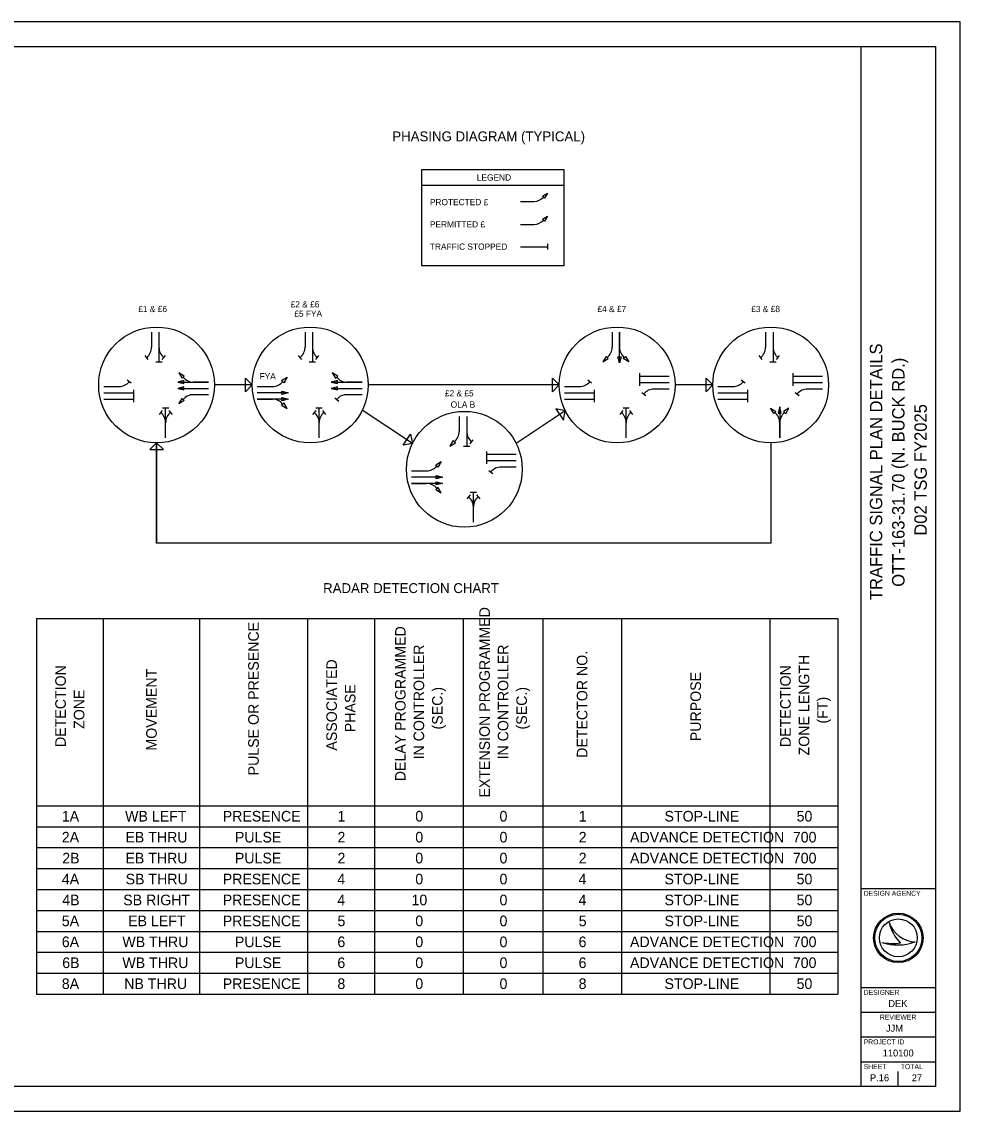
# Model space of a CAD drawing. Extents: x 0 to 680, y 0 to 440.
# Drawn here: x 300.9 to 680, y 0 to 440 of the extents above; entities that cross this region are included whole.
import ezdxf

# ---------------------------------------------------------------- set-up
doc = ezdxf.new("R2010")
doc.units = 0
for name, color, linetype in [('SH_Border', 7, 'Continuous'), ('SH_Cut_Line', 7, 'Continuous'), ('SH_Data', 7, 'Continuous'), ('SH_Text', 7, 'Continuous')]:
    doc.layers.add(name, color=color, linetype=linetype)

msp = doc.modelspace()

# ---------------------------------------------------------------- linework, layer by layer
at = {"layer": 'SH_Border'}
for p, q in [((640, 10), (640, 430)), ((640, 90), (670, 90)), ((640, 50), (670, 50)), ((640, 40), (670, 40)), ((640, 30), (670, 30)), ((640, 20), (670, 20))]:
    msp.add_line(p, q, dxfattribs=at)
msp.add_lwpolyline([(30, 430), (670, 430), (670, 10), (30, 10)], close=True, dxfattribs=at)
at = {"layer": 'SH_Cut_Line'}
msp.add_lwpolyline([(0, 0), (680, 0), (680, 440), (0, 440)], close=True, dxfattribs=at)
at = {"layer": 'SH_Data'}
for p, q in [((462.45, 373.97), (520.09, 373.97)), ((502.43, 367.44), (507.93, 367.44)), ((502.43, 358.14), (507.93, 358.14)), ((502.43, 349.14), (513.24, 349.14)), ((513.24, 350.28), (513.24, 348)), ((353.35, 314.68), (353.35, 308.57)), ((356.34, 314.68), (356.34, 308.57)), ((356.34, 314.68), (356.34, 302.67)), ((415.36, 314.68), (415.36, 308.57)), ((418.35, 314.68), (418.35, 308.57)), ((418.35, 314.68), (418.35, 302.67)), ((539.39, 314.68), (539.39, 308.57)), ((542.38, 314.68), (542.38, 308.57)), ((542.38, 302.22), (542.38, 314.68)), ((601.4, 314.68), (601.4, 308.57)), ((604.39, 314.68), (604.39, 308.57)), ((604.39, 314.68), (604.39, 302.67)), ((352.01, 303.64), (350.73, 305.24)), ((357.68, 303.64), (358.96, 305.24)), ((414.02, 303.64), (412.74, 305.24)), ((419.69, 303.64), (420.97, 305.24)), ((600.06, 303.64), (598.78, 305.24)), ((605.73, 303.64), (607.01, 305.24)), ((355.07, 302.67), (357.61, 302.67)), ((417.08, 302.67), (419.62, 302.67)), ((603.12, 302.67), (605.66, 302.67)), ((345.09, 294.01), (343.5, 295.29)), ((531.13, 294.01), (529.54, 295.29)), ((550.41, 298.02), (550.41, 295.49)), ((562.42, 296.76), (550.41, 296.76)), ((550.41, 295.49), (550.41, 292.95)), ((593.15, 294.01), (591.55, 295.29)), ((612.42, 298.02), (612.42, 295.49)), ((624.43, 296.76), (612.42, 296.76)), ((612.42, 295.49), (612.42, 292.95)), ((334.06, 292.66), (340.17, 292.67)), ((346.07, 291.4), (346.07, 288.86)), ((363.92, 294.47), (376.38, 294.47)), ((363.92, 291.94), (376.38, 291.94)), ((376.38, 294.47), (370.27, 294.47)), ((394.01, 293.32), (378.79, 293.32)), ((396.07, 292.66), (402.18, 292.66)), ((425.93, 294.47), (438.39, 294.47)), ((425.93, 291.94), (438.39, 291.94)), ((438.39, 294.47), (432.28, 294.47)), ((518.04, 293.32), (440.8, 293.32)), ((520.1, 292.66), (526.21, 292.67)), ((532.11, 291.4), (532.11, 288.86)), ((562.42, 294.22), (550.41, 294.22)), ((562.42, 291.68), (556.31, 291.68)), ((580.05, 293.32), (564.83, 293.32)), ((582.11, 292.66), (588.22, 292.67)), ((594.12, 291.4), (594.12, 288.86)), ((624.43, 294.22), (612.42, 294.22)), ((624.43, 291.68), (618.32, 291.68)), ((334.06, 290.13), (346.07, 290.13)), ((334.06, 287.59), (346.07, 287.59)), ((346.07, 288.86), (346.07, 286.32)), ((376.38, 289.4), (370.27, 289.4)), ((408.53, 290.13), (396.07, 290.13)), ((408.53, 287.59), (396.07, 287.59)), ((396.07, 287.59), (402.18, 287.59)), ((427.35, 288.06), (428.95, 286.78)), ((438.39, 289.4), (432.28, 289.4)), ((520.1, 290.13), (532.11, 290.13)), ((520.1, 287.59), (532.11, 287.59)), ((532.11, 288.86), (532.11, 286.32)), ((551.38, 290.34), (552.97, 289.06)), ((582.11, 290.13), (594.12, 290.13)), ((582.11, 287.59), (594.12, 287.59)), ((594.12, 288.86), (594.12, 286.32)), ((613.39, 290.34), (614.99, 289.06)), ((357.69, 283.02), (356.41, 281.42)), ((360.3, 283.99), (357.76, 283.99)), ((359.03, 271.98), (359.03, 283.99)), ((360.37, 283.02), (361.65, 281.42)), ((419.7, 283.02), (418.42, 281.42)), ((422.31, 283.99), (419.77, 283.99)), ((421.04, 271.98), (421.04, 283.99)), ((422.38, 283.02), (423.66, 281.42)), ((458.78, 269.73), (438.49, 283.18)), ((520.49, 282.9), (500.63, 269.73)), ((543.73, 283.02), (542.45, 281.42)), ((546.34, 283.99), (543.8, 283.99)), ((545.07, 271.98), (545.07, 283.99)), ((546.41, 283.02), (547.69, 281.42)), ((607.08, 284.44), (607.08, 271.98)), ((359.03, 271.98), (359.03, 278.09)), ((359.03, 271.98), (359.03, 278.09)), ((421.04, 271.98), (421.04, 278.09)), ((421.04, 271.98), (421.04, 278.09)), ((477.66, 280.63), (477.66, 274.52)), ((480.65, 280.63), (480.65, 268.62)), ((480.65, 280.63), (480.65, 274.52)), ((545.07, 271.98), (545.07, 278.09)), ((545.07, 271.98), (545.07, 278.09)), ((607.08, 271.98), (607.08, 278.09)), ((607.08, 271.98), (607.08, 278.09)), ((355.39, 269.92), (355.39, 229.36)), ((479.38, 268.62), (481.92, 268.62)), ((481.99, 269.59), (483.27, 271.19)), ((603.45, 269.92), (603.45, 229.36)), ((488.67, 266.51), (488.67, 263.97)), ((500.69, 265.24), (488.67, 265.24)), ((488.67, 263.97), (488.67, 261.44)), ((500.69, 262.71), (488.67, 262.71)), ((500.69, 260.17), (494.58, 260.17)), ((458.36, 258.62), (464.48, 258.62)), ((470.82, 256.08), (458.36, 256.08)), ((489.65, 258.83), (491.24, 257.55)), ((470.82, 253.54), (458.36, 253.54)), ((458.36, 253.54), (464.48, 253.54)), ((482, 248.97), (480.72, 247.38)), ((484.6, 249.94), (482.07, 249.94)), ((483.34, 237.93), (483.34, 249.94)), ((484.67, 248.97), (485.96, 247.38)), ((483.34, 237.93), (483.34, 244.04)), ((483.34, 237.93), (483.34, 244.04)), ((306.82, 199.03), (630.63, 199.03)), ((306.82, 199.03), (306.82, 47.27)), ((333.87, 199.03), (333.87, 47.27)), ((372.76, 199.03), (372.76, 47.27)), ((416.31, 199.03), (416.31, 47.27)), ((443.36, 199.03), (443.36, 47.27)), ((479.29, 199.03), (479.29, 47.27)), ((511.42, 199.03), (511.42, 47.27)), ((543.12, 199.03), (543.12, 47.27)), ((603.15, 199.03), (603.15, 47.27)), ((630.63, 199.03), (630.63, 47.27)), ((306.82, 123.36), (630.63, 123.36)), ((306.82, 114.91), (630.63, 114.91)), ((306.82, 106.45), (630.63, 106.45)), ((306.82, 98), (630.63, 98)), ((306.82, 89.55), (630.63, 89.55)), ((306.82, 81.09), (630.63, 81.09)), ((651.35, 76.19), (651.35, 76.19)), ((306.82, 72.64), (630.63, 72.64)), ((648.34, 68.19), (648.34, 68.19)), ((655, 70), (655, 70)), ((661.75, 68.37), (661.75, 68.37)), ((306.82, 64.18), (630.63, 64.18)), ((306.82, 55.73), (630.63, 55.73)), ((306.82, 47.27), (630.63, 47.27)), ((647.5, 13.5), (647.5, 13.5)), ((655, 10), (655, 16))]:
    msp.add_line(p, q, dxfattribs=at)
for points in [[(520.09, 380.27), (462.45, 380.27), (462.45, 341.58), (520.09, 341.58)], [(511.25, 369.62), (513.24, 370.82), (512.04, 368.83)], [(511.25, 360.32), (513.24, 361.51), (512.04, 359.52)], [(536.97, 304.88), (535.64, 302.67), (537.85, 304)], [(543, 304.72), (542.38, 302.22), (541.75, 304.72)], [(544.8, 304.88), (546.12, 302.67), (543.92, 304)], [(366.42, 295.1), (363.92, 294.47), (366.42, 293.85)], [(366.58, 296.9), (364.37, 298.22), (365.7, 296.01)], [(394.01, 293.32), (391.29, 290.59), (391.29, 296.04)], [(405.87, 295.09), (408.08, 296.41), (406.75, 294.2)], [(428.43, 295.1), (425.93, 294.47), (428.43, 293.85)], [(428.59, 296.9), (426.38, 298.22), (427.71, 296.01)], [(518.04, 293.32), (515.31, 290.59), (515.31, 296.04)], [(580.05, 293.32), (577.33, 290.59), (577.32, 296.04)], [(366.42, 292.56), (363.92, 291.94), (366.42, 291.31)], [(406.03, 290.75), (408.53, 290.13), (406.03, 289.5)], [(428.43, 292.56), (425.93, 291.94), (428.43, 291.31)], [(366.58, 286.98), (364.37, 285.65), (365.7, 287.86)], [(405.87, 285.17), (408.08, 283.84), (406.75, 286.05)], [(406.03, 288.22), (408.53, 287.59), (406.03, 286.97)], [(520.49, 282.9), (516.71, 283.66), (519.72, 279.12)], [(604.66, 281.78), (603.34, 283.99), (605.54, 282.66)], [(607.71, 281.94), (607.08, 284.44), (606.46, 281.94)], [(609.5, 281.78), (610.83, 283.99), (608.62, 282.66)], [(458.78, 269.73), (455, 268.96), (458.01, 273.51)], [(355.39, 269.92), (352.67, 267.2), (358.12, 267.19)], [(475.24, 270.83), (473.91, 268.62), (476.12, 269.95)], [(468.16, 261.04), (470.38, 262.36), (469.05, 260.16)], [(468.32, 256.71), (470.82, 256.08), (468.32, 255.45)], [(468.16, 251.12), (470.38, 249.8), (469.05, 252)], [(468.32, 254.17), (470.82, 253.54), (468.32, 252.92)]]:
    msp.add_lwpolyline(points, close=True, dxfattribs=at)
msp.add_lwpolyline([(603.45, 269.92), (603.45, 269.92), (603.45, 229.36), (355.39, 229.36), (355.39, 229.36), (355.39, 269.92), (355.39, 269.92)], dxfattribs=at)
for centre, radius in [((355.39, 293.32), 23.39), ((417.41, 293.32), 23.39), ((541.43, 293.32), 23.39), ((603.45, 293.32), 23.39), ((479.7, 259.27), 23.39), ((655, 70), 10), ((655, 70), 9.54), ((655, 70), 9.54), ((655, 70), 7.64)]:
    msp.add_circle(centre, radius, dxfattribs=at)
for centre, radius, start, end in [((507.93, 372.21), 4.77, 270.0129, 321.2136), ((507.93, 362.91), 4.77, 270, 321.2007), ((348.05, 308.57), 5.3, 308.7993, 0), ((361.64, 308.57), 5.3, 180, 231.2007), ((410.06, 308.57), 5.3, 308.7993, 0), ((423.65, 308.57), 5.3, 180, 231.2007), ((534.09, 308.57), 5.3, 308.7993, 0), ((547.68, 308.57), 5.3, 180, 231.2007), ((596.1, 308.57), 5.3, 308.7993, 0), ((609.69, 308.57), 5.3, 180, 231.2007), ((370.27, 299.77), 5.3, 218.7864, 269.9871), ((432.28, 299.77), 5.3, 218.7864, 269.9871), ((340.17, 297.97), 5.3, 270.0129, 321.2136), ((402.18, 297.96), 5.3, 270, 321.2007), ((526.21, 297.97), 5.3, 270.0129, 321.2136), ((556.31, 286.38), 5.3, 90.0129, 141.2136), ((588.22, 297.97), 5.3, 270.0129, 321.2136), ((618.32, 286.38), 5.3, 90.0129, 141.2136), ((370.27, 284.1), 5.3, 90.0129, 141.2136), ((402.18, 282.29), 5.3, 38.7864, 89.9871), ((432.28, 284.1), 5.3, 90.0129, 141.2136), ((353.73, 278.09), 5.3, 360, 51.2007), ((364.33, 278.09), 5.3, 128.7993, 180), ((415.74, 278.09), 5.3, 360, 51.2007), ((426.34, 278.09), 5.3, 128.7993, 180), ((539.77, 278.09), 5.3, 360, 51.2007), ((550.37, 278.09), 5.3, 128.7993, 180), ((601.78, 278.09), 5.3, 360, 51.2007), ((612.38, 278.09), 5.3, 128.7993, 180), ((472.36, 274.52), 5.3, 308.7993, 0), ((485.95, 274.52), 5.3, 180, 231.2007), ((464.47, 263.92), 5.3, 270.0129, 321.2136), ((494.58, 254.87), 5.3, 90.0129, 141.2136), ((464.47, 248.24), 5.3, 38.7864, 89.9871), ((478.04, 244.04), 5.3, 360, 51.2007), ((488.64, 244.04), 5.3, 128.7993, 180), ((662.32, 79.95), 11.6, 198.9257, 198.9319), ((666.93, 79.4), 15.91, 191.6379, 191.6421), ((662.32, 79.95), 11.6, 198.9319, 267.1657), ((666.93, 79.4), 15.91, 191.6421, 226.0947), ((654.79, 87.4), 20.26, 251.4576, 290.0832), ((652.96, 93.09), 25.32, 259.4964, 259.4995), ((654.79, 87.4), 20.26, 251.4527, 251.4576), ((652.96, 93.09), 25.32, 259.4995, 276.6672)]:
    msp.add_arc(centre, radius, start, end, dxfattribs=at)

# ---------------------------------------------------------------- texts
for s, height, p in [('TRAFFIC SIGNAL PLAN DETAILS', 5, (648.5, 206.42)), ('OTT-163-31.70 (N. BUCK RD.)', 5, (657.5, 211.8)), ('D02 TSG FY2025', 5, (666.5, 232.44)), ('EXTENSION PROGRAMMED', 4.278, (490.01, 126.68)), ('PULSE OR PRESENCE', 4.278, (396.67, 135.64)), ('DELAY PROGRAMMED', 4.278, (455.98, 133.26)), (' IN CONTROLLER', 4.278, (463.47, 140.48)), (' IN CONTROLLER', 4.278, (497.49, 140.48)), ('DETECTOR NO.', 4.278, (529.41, 142.71)), ('ASSOCIATED', 4.278, (428.23, 145.64)), ('ZONE LENGTH', 4.278, (619.03, 143.69)), ('DETECTION', 4.278, (318.74, 147.1)), ('MOVEMENT', 4.278, (355.46, 145.66)), ('PURPOSE', 4.278, (575.28, 149.45)), ('DETECTION', 4.278, (611.54, 147.1)), ('PHASE', 4.278, (435.71, 153.05)), ('ZONE', 4.278, (326.23, 154.4)), ('(SEC.)', 4.278, (470.95, 154.18)), ('(SEC.)', 4.278, (504.98, 154.18)), ('(FT)', 4.278, (626.52, 156.57))]:
    msp.add_text(s, height=height, rotation=90, dxfattribs=at).set_placement(p)
for s, height, p in [('1A', 4.278, (317.11, 117)), ('WB LEFT', 4.278, (342.68, 117)), ('PRESENCE', 4.278, (382.1, 117)), ('1', 4.28, (428.46, 117)), ('0', 4.28, (459.89, 117)), ('0', 4.28, (493.92, 117)), ('1', 4.28, (525.9, 117)), ('STOP-LINE', 4.278, (560.55, 117)), ('50', 4.278, (613.92, 117)), ('2A', 4.278, (317.11, 108.54)), ('EB THRU', 4.278, (342.79, 108.54)), ('PULSE', 4.278, (387.03, 108.54)), ('2', 4.28, (428.46, 108.54)), ('0', 4.28, (459.89, 108.54)), ('0', 4.28, (493.92, 108.54)), ('2', 4.28, (525.9, 108.54)), ('ADVANCE DETECTION', 4.278, (546.62, 108.54)), ('700', 4.278, (612.39, 108.54)), ('2B', 4.278, (317.29, 100.09)), ('EB THRU', 4.278, (342.79, 100.09)), ('PULSE', 4.278, (387.03, 100.09)), ('2', 4.28, (428.46, 100.09)), ('0', 4.28, (459.89, 100.09)), ('0', 4.28, (493.92, 100.09)), ('2', 4.28, (525.9, 100.09)), ('ADVANCE DETECTION', 4.278, (546.62, 100.09)), ('700', 4.278, (612.39, 100.09)), ('4A', 4.278, (317.11, 91.63)), ('SB THRU', 4.278, (342.88, 91.63)), ('PRESENCE', 4.278, (382.1, 91.63)), ('4', 4.28, (428.38, 91.63)), ('0', 4.28, (459.89, 91.63)), ('0', 4.28, (493.92, 91.63)), ('4', 4.28, (525.82, 91.63)), ('STOP-LINE', 4.278, (560.55, 91.63)), ('50', 4.278, (613.92, 91.63)), ('DESIGN AGENCY', 2, (641, 87)), ('4B', 4.278, (317.29, 83.18)), ('SB RIGHT', 4.278, (341.92, 83.18)), ('PRESENCE', 4.278, (382.1, 83.18)), ('4', 4.28, (428.38, 83.18)), ('10', 4.278, (458.36, 83.18)), ('0', 4.28, (493.92, 83.18)), ('4', 4.28, (525.82, 83.18)), ('STOP-LINE', 4.278, (560.55, 83.18)), ('50', 4.278, (613.92, 83.18)), ('5A', 4.278, (317.11, 74.72)), ('EB LEFT', 4.278, (343.9, 74.72)), ('PRESENCE', 4.278, (382.1, 74.72)), ('5', 4.28, (428.47, 74.72)), ('0', 4.28, (459.89, 74.72)), ('0', 4.28, (493.92, 74.72)), ('5', 4.28, (525.91, 74.72)), ('STOP-LINE', 4.278, (560.55, 74.72)), ('50', 4.278, (613.92, 74.72)), ('6A', 4.278, (317.11, 66.27)), ('WB THRU', 4.278, (341.57, 66.27)), ('PULSE', 4.278, (387.03, 66.27)), ('6', 4.28, (428.42, 66.27)), ('0', 4.28, (459.89, 66.27)), ('0', 4.28, (493.92, 66.27)), ('6', 4.28, (525.85, 66.27)), ('ADVANCE DETECTION', 4.278, (546.62, 66.27)), ('700', 4.278, (612.39, 66.27)), ('6B', 4.278, (317.29, 57.82)), ('WB THRU', 4.278, (341.57, 57.82)), ('PULSE', 4.278, (387.03, 57.82)), ('6', 4.28, (428.42, 57.82)), ('0', 4.28, (459.89, 57.82)), ('0', 4.28, (493.92, 57.82)), ('6', 4.28, (525.85, 57.82)), ('ADVANCE DETECTION', 4.278, (546.62, 57.82)), ('700', 4.278, (612.39, 57.82)), ('8A', 4.278, (317.11, 49.36)), ('NB THRU', 4.278, (342.32, 49.36)), ('PRESENCE', 4.278, (382.1, 49.36)), ('8', 4.28, (428.42, 49.36)), ('0', 4.28, (459.89, 49.36)), ('0', 4.28, (493.92, 49.36)), ('8', 4.28, (525.86, 49.36)), ('STOP-LINE', 4.278, (560.55, 49.36)), ('50', 4.278, (613.92, 49.36)), ('DESIGNER', 2, (641, 47)), ('DEK', 2.8, (650.98, 42.1)), ('REVIEWER', 2, (647.57, 37)), ('                 JJM', 2.8, (632.33, 32.1)), ('PROJECT ID', 2, (641, 27)), ('110100', 2.8, (648.71, 22.1)), ('SHEET', 2, (641, 17)), ('TOTAL', 2, (656, 17)), ('P.16', 2.8, (643.57, 12.1)), ('27', 2.8, (660.41, 12.1))]:
    msp.add_text(s, height=height, dxfattribs=at).set_placement(p)
at = {"layer": 'SH_Text'}
for s, height, p in [('PHASING DIAGRAM (TYPICAL)', 4, (450.59, 391.72)), ('LEGEND', 2.52, (484.74, 375.86)), ('PROTECTED £', 2.52, (465.78, 365.93)), ('PERMITTED £', 2.52, (465.78, 356.93)), ('TRAFFIC STOPPED', 2.52, (465.78, 347.93)), ('£2 & £6', 2.52, (409.53, 324.63)), ('£1 & £6', 2.52, (348, 322.74)), ('£5 FYA', 2.52, (411.02, 320.85)), ('£4 & £7', 2.52, (533.48, 322.74)), ('£3 & £8', 2.52, (595.59, 322.74)), ('FYA', 2.52, (396.98, 295.57)), ('£2 & £5', 2.52, (471.84, 288.69)), ('OLA B', 2.52, (474.18, 284.15)), ('RADAR DETECTION CHART', 4, (422.65, 209.27))]:
    msp.add_text(s, height=height, dxfattribs=at).set_placement(p)

doc.saveas('drawing.dxf')
